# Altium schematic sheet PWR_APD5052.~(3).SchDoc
size A4
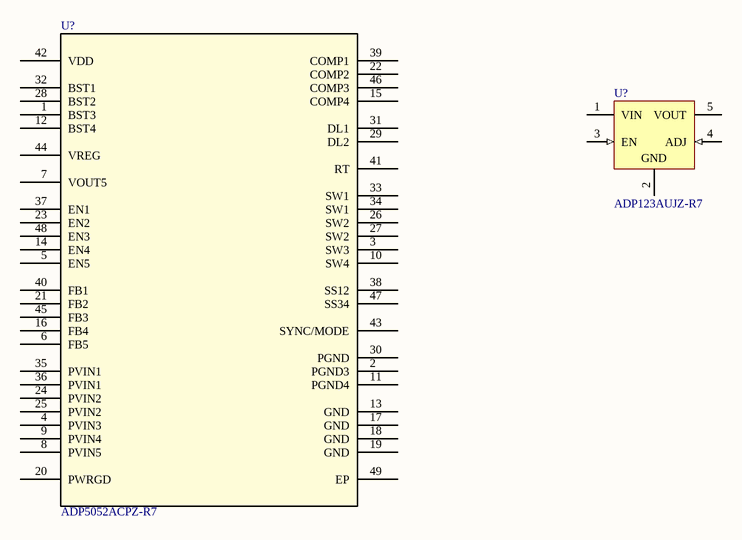
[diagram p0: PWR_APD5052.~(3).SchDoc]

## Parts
(Parts that share a designator on the sheet are numbered #1, #2 ... from top to bottom, then left to right.)
U?#1  ADP5052ACPZ-R7  [CP_48_13]
U?#2  ADP123AUJZ-R7  [ADI-UJ-5_N]

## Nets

Not connected (* = marked no-connect by the designer): U?#1 1(BST3) 2(PGND3) 3(SW3) 4(PVIN3) 5(EN5) 6(FB5) 7(VOUT5) 8(PVIN5) 9(PVIN4) 10(SW4) 11(PGND4) 12(BST4) 13(GND) 14(EN4) 15(COMP4) 16(FB4) 17(GND) 18(GND) 19(GND) 20(PWRGD) 21(FB2) 22(COMP2) 23(EN2) 24(PVIN2) 25(PVIN2) 26(SW2) 27(SW2) 28(BST2) 29(DL2) 30(PGND) 31(DL1) 32(BST1) 33(SW1) 34(SW1) 35(PVIN1) 36(PVIN1) 37(EN1) 38(SS12) 39(COMP1) 40(FB1) 41(RT) 42(VDD) 43(SYNC/MODE) 44(VREG) 45(FB3) 46(COMP3) 47(SS34) 48(EN3) 49(EP); U?#2 1(VIN) 2(GND) 3(EN) 4(ADJ) 5(VOUT)

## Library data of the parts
U?#1 = ADP5052ACPZ-R7: Imported
U?#2 = ADP123AUJZ-R7: 300 mA, Low Quiescent Current, CMOS Linear Regulator, 2.3 to 5.5 V Vin, 0.8 to 5 V Vout, Industrial, 5-pin SOT23 (UJ-5), Reel; Manufacturer: Analog Devices; Iout max: 300mA; Supply Current IGND @ Small Load: 45uA; Vin (max) (V): 5.5; Vin (min) (V): 2.3; Vout Adjustable Range: 0.8V to 5V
